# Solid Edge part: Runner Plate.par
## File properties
Author: Dan
Template: metric part.par
Last saved by: Dan
Revision: 34
Application: Solid Edge
Density: 7833.000 kg/m^3
Accuracy: 0.990
Material: Steel
Face Style: Steel
Fill Style: ANSI32(Steel)
Virtual Style: Machined steel
Coef. of Thermal Exp: 1.3e-05
Thermal Conductivity: 32.0
Specific Heat: 481.0
Modulus of Elasticity: 199947953000.0
Poisson's Ratio: 0.29
Yield Stress: 262000766.0
Ultimate Stress: 358527364.0
Elongation: 0.0
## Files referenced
..\Fixed Half.asm
C:\Drawing Files Other\Dave\Tente\HUP 125X36H45-TSA 02-07-2011\Wheel Mould\FH insert Outer.par
YC:\Drawing Files Other\Dave\Tente\HUP 125X36H45-TSA 02-07-2011\Wheel Mould\Fixed Half.asm
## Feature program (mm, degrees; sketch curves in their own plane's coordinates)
sketch for "unnamed Protrusion 1" plane through (0, 0, 0) normal (0, 0, 1) x-axis (1, 0, 0)
extrude "unnamed Protrusion 1" add finite 26 along -normal
sketch for "Hole_9" plane through (-12.9045, 10.6284, 0) normal (0, 0, 1) x-axis (1, 0, 0)
hole "Hole_9" diameter 42 through  CounterBoreDepth = 6 mm; VBottomAngle = 118 deg
sketch for "unnamed Hole 1" plane through (-12.9045, 10.6284, 0) normal (0, 0, 1) x-axis (1, 0, 0)
hole "unnamed Hole 1" through
sketch for "unnamed Hole 2" plane through (-12.9045, 10.6284, 0) normal (0, 0, 1) x-axis (1, 0, 0)
hole "unnamed Hole 2" through
sketch for "unnamed Hole 3" plane through (-12.9045, 10.6284, 0) normal (0, 0, 1) x-axis (1, 0, 0)
  hole centre (182.9045, -180.6284) bore radius 21
hole "unnamed Hole 3" through
pattern "unnamed Pattern 1" of "Hole_9", "unnamed Hole 1", "unnamed Hole 2", "unnamed Hole 3"
sketch for "Hole_13" plane through (0, 0, -26) normal (0, 0, -1) x-axis (-1, 0, 0)
hole "Hole_13" diameter 26 through  VBottomAngle = 118 deg
sketch for "unnamed Hole 4" plane through (0, 0, -26) normal (0, 0, -1) x-axis (-1, 0, 0)
hole "unnamed Hole 4" through
sketch for "unnamed Hole 5" plane through (0, 0, -26) normal (0, 0, -1) x-axis (-1, 0, 0)
  hole centre (170, 106) bore radius 13
hole "unnamed Hole 5" through
sketch for "unnamed Hole 6" plane through (0, 0, -26) normal (0, 0, -1) x-axis (-1, 0, 0)
  hole centre (170, -106) bore radius 13
hole "unnamed Hole 6" through
pattern "unnamed Pattern 2" of "Hole_13", "unnamed Hole 4", "unnamed Hole 5", "unnamed Hole 6"
sketch for "Hole_33" plane through (0, 0, -26) normal (0, 0, -1) x-axis (-1, 0, 0)
  hole centre (109.2946, 40.7053) bore radius 1.025
hole "Hole_33" finite  TaperAngle = 3 deg
sketch for "unnamed Hole 7" plane through (0, 0, -26) normal (0, 0, -1) x-axis (-1, 0, 0)
  hole centre (95.5061, 54.4939) bore radius 1.025
hole "unnamed Hole 7" finite
sketch for "unnamed Hole 8" plane through (0, 0, -26) normal (0, 0, -1) x-axis (-1, 0, 0)
  hole centre (54.4939, 54.4939) bore radius 1.025
hole "unnamed Hole 8" finite
sketch for "unnamed Hole 9" plane through (0, 0, -26) normal (0, 0, -1) x-axis (-1, 0, 0)
  hole centre (40.7053, 40.7054) bore radius 1.025
hole "unnamed Hole 9" finite
sketch for "unnamed Hole 10" plane through (0, 0, -26) normal (0, 0, -1) x-axis (-1, 0, 0)
  hole centre (54.4939, 95.5061) bore radius 1.025
hole "unnamed Hole 10" finite
sketch for "unnamed Hole 11" plane through (0, 0, -26) normal (0, 0, -1) x-axis (-1, 0, 0)
  hole centre (40.7054, 109.2947) bore radius 1.025
hole "unnamed Hole 11" finite
sketch for "unnamed Hole 12" plane through (0, 0, -26) normal (0, 0, -1) x-axis (-1, 0, 0)
  hole centre (95.5061, 95.5061) bore radius 1.025
hole "unnamed Hole 12" finite
sketch for "unnamed Hole 13" plane through (0, 0, -26) normal (0, 0, -1) x-axis (-1, 0, 0)
  hole centre (109.2947, 109.2946) bore radius 1.025
hole "unnamed Hole 13" finite
pattern "unnamed Pattern 3" of "Hole_33", "unnamed Hole 7", "unnamed Hole 8", "unnamed Hole 9", "unnamed Hole 10", "unnamed Hole 11", "unnamed Hole 12", "unnamed Hole 13"
sketch for "ExtrudedCutout_2" #1 plane through (0, 0, -26) normal (0, 0, -1) x-axis (-1, 0, 0)
  line (-2.323, 2.4731) -> (106.8181, 111.7678)
  arc centre (0.1536, 0) radius 3.5 from (2.6302, -2.4731) to (-2.323, 2.4731) cw
  line (2.6302, -2.4731) -> (111.7713, 106.8215)
  arc centre (109.2947, 109.2946) radius 3.5 from (106.8181, 111.7678) to (111.7713, 106.8215) cw
sketch for "ExtrudedCutout_2" #2 plane through (0, 0, -26) normal (0, 0, -1) x-axis (-1, 0, 0)
  line (43.1802, 111.7695) -> (111.7695, 43.1802)
  arc centre (40.7054, 109.2947) radius 3.5 from (38.2305, 106.8198) to (43.1802, 111.7695) cw
  line (38.2305, 106.8198) -> (106.8198, 38.2305)
  arc centre (109.2946, 40.7053) radius 3.5 from (111.7695, 43.1802) to (106.8198, 38.2305) cw
extrude "ExtrudedCutout_2" cut finite 4 along -normal  Treatment1_DraftAngle = 15 deg
pattern "unnamed Pattern 4" of "unnamed Pattern 3", "ExtrudedCutout_2"
hole "unnamed Hole 14" finite
hole "unnamed Hole 15" finite
hole "unnamed Hole 16" finite
hole "unnamed Hole 17" finite
hole "unnamed Hole 18" finite
hole "unnamed Hole 19" finite
hole "unnamed Hole 20" finite
hole "unnamed Hole 21" finite
extrude "unnamed Cutout 1" cut finite 4
hole "unnamed Hole 22" finite
hole "unnamed Hole 23" finite
hole "unnamed Hole 24" finite
hole "unnamed Hole 25" finite
hole "unnamed Hole 26" finite
hole "unnamed Hole 27" finite
hole "unnamed Hole 28" finite
hole "unnamed Hole 29" finite
extrude "unnamed Cutout 2" cut finite 4
hole "unnamed Hole 30" finite
hole "unnamed Hole 31" finite
hole "unnamed Hole 32" finite
hole "unnamed Hole 33" finite
hole "unnamed Hole 34" finite
hole "unnamed Hole 35" finite
hole "unnamed Hole 36" finite
hole "unnamed Hole 37" finite
extrude "unnamed Cutout 3" cut finite 4
sketch for "Hole_77" plane through (0, 0, -26) normal (0, 0, -1) x-axis (-1, 0, 0)
hole "Hole_77" diameter 6.5 through  CounterBoreDepth = 6.5 mm
sketch for "unnamed Hole 38" plane through (0, 0, -26) normal (0, 0, -1) x-axis (-1, 0, 0)
hole "unnamed Hole 38" through
sketch for "unnamed Hole 39" plane through (0, 0, -26) normal (0, 0, -1) x-axis (-1, 0, 0)
  hole centre (-91.084, 35.1552) bore radius 3.25
hole "unnamed Hole 39" through
sketch for "unnamed Hole 40" plane through (0, 0, -26) normal (0, 0, -1) x-axis (-1, 0, 0)
  hole centre (-58.8678, 114.893) bore radius 3.25
hole "unnamed Hole 40" through
sketch for "unnamed Hole 41" plane through (0, 0, -26) normal (0, 0, -1) x-axis (-1, 0, 0)
hole "unnamed Hole 41" through
sketch for "unnamed Hole 42" plane through (0, 0, -26) normal (0, 0, -1) x-axis (-1, 0, 0)
  hole centre (-114.8448, -58.8678) bore radius 3.25
hole "unnamed Hole 42" through
sketch for "unnamed Hole 43" plane through (0, 0, -26) normal (0, 0, -1) x-axis (-1, 0, 0)
  hole centre (-91.084, -114.8448) bore radius 3.25
hole "unnamed Hole 43" through
sketch for "unnamed Hole 44" plane through (0, 0, -26) normal (0, 0, -1) x-axis (-1, 0, 0)
  hole centre (-35.107, -91.084) bore radius 3.25
hole "unnamed Hole 44" through
sketch for "unnamed Hole 45" plane through (0, 0, -26) normal (0, 0, -1) x-axis (-1, 0, 0)
  hole centre (-58.8678, -35.107) bore radius 3.25
hole "unnamed Hole 45" through
sketch for "unnamed Hole 46" plane through (0, 0, -26) normal (0, 0, -1) x-axis (-1, 0, 0)
  hole centre (91.1322, -35.107) bore radius 3.25
hole "unnamed Hole 46" through
sketch for "unnamed Hole 47" plane through (0, 0, -26) normal (0, 0, -1) x-axis (-1, 0, 0)
  hole centre (35.1552, -58.8678) bore radius 3.25
hole "unnamed Hole 47" through
sketch for "unnamed Hole 48" plane through (0, 0, -26) normal (0, 0, -1) x-axis (-1, 0, 0)
  hole centre (58.916, -114.8448) bore radius 3.25
hole "unnamed Hole 48" through
sketch for "unnamed Hole 49" plane through (0, 0, -26) normal (0, 0, -1) x-axis (-1, 0, 0)
  hole centre (114.893, -91.084) bore radius 3.25
hole "unnamed Hole 49" through
sketch for "unnamed Hole 50" plane through (0, 0, -26) normal (0, 0, -1) x-axis (-1, 0, 0)
  hole centre (114.893, 58.916) bore radius 3.25
hole "unnamed Hole 50" through
sketch for "unnamed Hole 51" plane through (0, 0, -26) normal (0, 0, -1) x-axis (-1, 0, 0)
  hole centre (58.916, 35.1552) bore radius 3.25
hole "unnamed Hole 51" through
sketch for "unnamed Hole 52" plane through (0, 0, -26) normal (0, 0, -1) x-axis (-1, 0, 0)
hole "unnamed Hole 52" through
pattern "unnamed Pattern 5" of "Hole_77", "unnamed Hole 38", "unnamed Hole 39", "unnamed Hole 40", "unnamed Hole 41", "unnamed Hole 42", "unnamed Hole 43", "unnamed Hole 44", "unnamed Hole 45", "unnamed Hole 46", "unnamed Hole 47", "unnamed Hole 48"
sketch for "Hole_93" plane through (0, 0, 0) normal (1, 0, 0) x-axis (0, 1, 0)
  hole centre (-75, -8) bore radius 3
hole "Hole_93" diameter 6 through  VBottomAngle = 118 deg
sketch for "unnamed Hole 53" plane through (0, 0, 0) normal (1, 0, 0) x-axis (0, 1, 0)
  hole centre (75, -8) bore radius 3
hole "unnamed Hole 53" through
pattern "unnamed Pattern 6" of "Hole_93", "unnamed Hole 53"
sketch for "Hole_95" plane through (0, 0, 0) normal (0, 0, 1) x-axis (1, 0, 0)
  hole centre (-75, 75) bore radius 9
hole "Hole_95" diameter 18 finite
sketch for "unnamed Hole 54" plane through (0, 0, 0) normal (0, 0, 1) x-axis (1, 0, 0)
  hole centre (-75, -75) bore radius 9
hole "unnamed Hole 54" finite
sketch for "unnamed Hole 55" plane through (0, 0, 0) normal (0, 0, 1) x-axis (1, 0, 0)
  hole centre (75, -75) bore radius 9
hole "unnamed Hole 55" finite
sketch for "unnamed Hole 56" plane through (0, 0, 0) normal (0, 0, 1) x-axis (1, 0, 0)
  hole centre (75, 75) bore radius 9
hole "unnamed Hole 56" finite
pattern "unnamed Pattern 7" of "Hole_95", "unnamed Hole 54", "unnamed Hole 55", "unnamed Hole 56"
sketch for "Hole_99" plane through (0, 0, 0) normal (0, 0, 1) x-axis (1, 0, 0)
  hole centre (-120, 180) bore radius 4.188
hole "Hole_99" nominal diameter 10 finite  VBottomAngle = 118 deg
sketch for "unnamed Hole 57" plane through (0, 0, 0) normal (0, 0, 1) x-axis (1, 0, 0)
  hole centre (120, 180) bore radius 4.188
hole "unnamed Hole 57" finite
sketch for "unnamed Hole 58" plane through (0, 0, 0) normal (0, 0, 1) x-axis (1, 0, 0)
  hole centre (120, -180) bore radius 4.188
hole "unnamed Hole 58" finite
sketch for "unnamed Hole 59" plane through (0, 0, 0) normal (0, 0, 1) x-axis (1, 0, 0)
  hole centre (-120, -180) bore radius 4.188
hole "unnamed Hole 59" finite
sketch for "unnamed Hole 60" plane through (0, 0, 0) normal (0, 0, 1) x-axis (1, 0, 0)
  hole centre (25, 0) bore radius 4.188
hole "unnamed Hole 60" finite
sketch for "unnamed Hole 61" plane through (0, 0, 0) normal (0, 0, 1) x-axis (1, 0, 0)
  hole centre (-25, 0) bore radius 4.188
hole "unnamed Hole 61" finite
pattern "unnamed Pattern 8" of "Hole_99", "unnamed Hole 57", "unnamed Hole 58", "unnamed Hole 59", "unnamed Hole 60", "unnamed Hole 61"
sketch for "Hole_105" plane through (0, 0, 0) normal (0, 0, 1) x-axis (1, 0, 0)
  hole centre (-75, 120) bore radius 3
hole "Hole_105" diameter 6 finite  VBottomAngle = 118 deg
sketch for "unnamed Hole 62" plane through (0, 0, 0) normal (0, 0, 1) x-axis (1, 0, 0)
hole "unnamed Hole 62" finite
sketch for "unnamed Hole 63" plane through (0, 0, 0) normal (0, 0, 1) x-axis (1, 0, 0)
  hole centre (-75, 30) bore radius 3
hole "unnamed Hole 63" finite
sketch for "unnamed Hole 64" plane through (0, 0, 0) normal (0, 0, 1) x-axis (1, 0, 0)
  hole centre (75, 30) bore radius 3
hole "unnamed Hole 64" finite
sketch for "unnamed Hole 65" plane through (0, 0, 0) normal (0, 0, 1) x-axis (1, 0, 0)
  hole centre (75, 120) bore radius 3
hole "unnamed Hole 65" finite
sketch for "unnamed Hole 66" plane through (0, 0, 0) normal (0, 0, 1) x-axis (1, 0, 0)
  hole centre (75, -30) bore radius 3
hole "unnamed Hole 66" finite
sketch for "unnamed Hole 67" plane through (0, 0, 0) normal (0, 0, 1) x-axis (1, 0, 0)
  hole centre (75, -120) bore radius 3
hole "unnamed Hole 67" finite
sketch for "unnamed Hole 68" plane through (0, 0, 0) normal (0, 0, 1) x-axis (1, 0, 0)
  hole centre (-75, -120) bore radius 3
hole "unnamed Hole 68" finite
pattern "unnamed Pattern 9" of "Hole_105", "unnamed Hole 62", "unnamed Hole 63", "unnamed Hole 64", "unnamed Hole 65", "unnamed Hole 66", "unnamed Hole 67", "unnamed Hole 68"
Other named dimensions: "Hole_17": Diameter = 2.05 mm
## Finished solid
Body 1: solid body, 209 faces, 472 edges, 208 vertices.
  Faces by surface: plane 83, cylinder 68, cone 58
  Edges by curve: circle 240, line 160, ellipse 64, intersection 8
Bounding box of the edges (mm): 396.000 x 396.000 x 26.000, from (-198, -198, -26) to (198, 198, 0).
Cylindrical faces by radius (mm): R3 x14, R3.25 x16, R4.188 x6, R6 x16, R9 x4, R13 x4, R21 x4, R23.5 x4
Conical faces (half-angle, radius in mm at the cone's reference point): 3 deg R1.025 x32, 15 deg R3.5 x12, 59 deg R3 x8, 59 deg R4.188 x6
Planar faces by outward normal: +x 1, +y 1, +z 9, -x 1, -y 1, -z 38, oblique 32
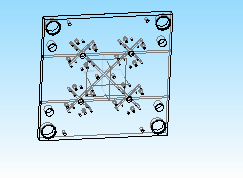
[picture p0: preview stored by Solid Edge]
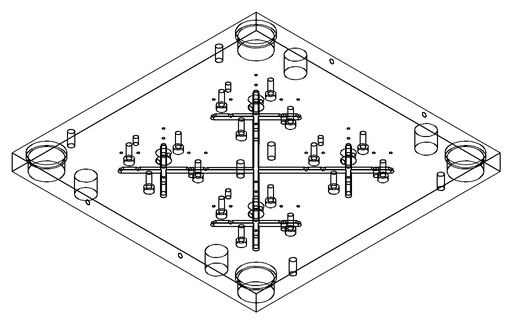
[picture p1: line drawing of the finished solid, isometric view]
